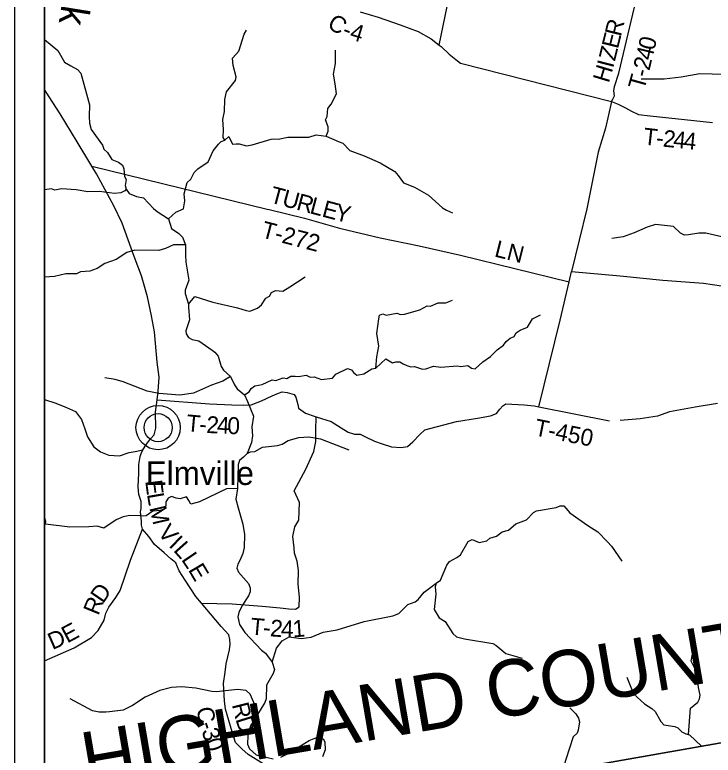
# Model space of a CAD drawing. Extents: x 0 to 34, y 0 to 22.
# Drawn here: x 23.917 to 26.267, y 14.865 to 17.356 of the extents above; entities that cross this region are included whole.
import ezdxf

# ---------------------------------------------------------------- set-up
doc = ezdxf.new("R2010")
doc.units = 0
for name, color, linetype in [('GM_X_Adjacent_County', 7, 'Continuous'), ('GM_X_Adjacent_County_Text', 7, 'Continuous'), ('GM_X_County', 7, 'Continuous'), ('GM_X_County_Road', 7, 'Continuous'), ('GM_X_County_Road_Text', 7, 'Continuous'), ('GM_X_Minor_River', 7, 'Continuous'), ('GM_X_Minor_River_Text', 7, 'Continuous'), ('GM_X_Township', 7, 'Continuous'), ('GM_X_Township_Road', 7, 'Continuous'), ('GM_X_Township_Road_Text', 7, 'Continuous'), ('GM_X_Township_ROW', 7, 'Continuous'), ('GM_X_Unincorporated', 7, 'Continuous'), ('GM_X_Unincorporated_Location', 7, 'Continuous'), ('GM_X_Unincorporated_Text', 7, 'Continuous'), ('SH_Data', 7, 'Continuous')]:
    doc.layers.add(name, color=color, linetype=linetype)

msp = doc.modelspace()

# ---------------------------------------------------------------- linework, layer by layer
at = {"layer": 'GM_X_Adjacent_County'}
msp.add_lwpolyline([(30.8167, 15.0595), (30.2392, 15.0941), (29.7209, 15.1252), (29.5448, 15.1357), (28.5345, 15.206), (28.3274, 15.217), (27.9456, 15.2665), (27.6234, 15.1875), (26.4461, 14.9325), (26.4085, 14.9262), (24.8262, 14.6485), (24.6978, 14.628), (24.0167, 14.5214)], dxfattribs=at)
at = {"layer": 'GM_X_County'}
for points in [[(29.025, 20.9), (24.0167, 20.9), (24.0167, 14.5214)], [(24.0167, 14.5214), (24.6978, 14.628), (24.8262, 14.6485), (26.4085, 14.9262), (26.4461, 14.9325), (27.6234, 15.1875), (27.9456, 15.2665), (27.9998, 15.5735), (28.0039, 15.594), (28.1843, 16.461), (28.2182, 16.6548), (28.4154, 17.5565), (28.5665, 18.3656), (28.8745, 20.061), (28.9523, 20.4546), (29.025, 20.9)]]:
    msp.add_lwpolyline(points, dxfattribs=at)
at = {"layer": 'GM_X_County_Road'}
for points in [[(25.0789, 17.3659), (25.1397, 17.3485), (25.213, 17.322), (25.2738, 17.3003), (25.3176, 17.2748), (25.3447, 17.254), (25.3515, 17.2488), (25.3786, 17.2235), (25.4003, 17.2055), (25.416, 17.193), (25.9245, 17.064), (25.9043, 16.9743), (25.8794, 16.8937), (25.8419, 16.7033), (25.7902, 16.4928), (25.9534, 16.4775), (26.0976, 16.4631), (26.2341, 16.4526), (26.2949, 16.4439)], [(24.7521, 14.8359), (24.7018, 14.8675), (24.6801, 14.886), (24.6598, 14.9079), (24.6482, 14.9435), (24.6257, 15.0196), (24.6218, 15.0477), (24.6191, 15.1065), (24.6249, 15.1445), (24.6278, 15.1726), (24.6337, 15.1954), (24.6389, 15.2193), (24.641, 15.2383), (24.6398, 15.2542), (24.637, 15.2694), (24.6114, 15.2977), (24.5447, 15.3763), (24.5255, 15.3989), (24.4898, 15.4533), (24.4703, 15.4851), (24.4587, 15.5116), (24.442, 15.5259), (24.4191, 15.5455), (24.3863, 15.5741), (24.3675, 15.6006), (24.3461, 15.6259), (24.3434, 15.6391), (24.3425, 15.6524), (24.3401, 15.6839), (24.3415, 15.6945), (24.3414, 15.7181), (24.3336, 15.7423), (24.3319, 15.7673), (24.3339, 15.8136), (24.3345, 15.8429), (24.3381, 15.8695), (24.3415, 15.8801), (24.3478, 15.8923), (24.3594, 15.9117), (24.3734, 15.9296), (24.3854, 15.9426), (24.391, 15.9654), (24.3898, 16.0193), (24.3955, 16.0607), (24.3993, 16.0884), (24.4024, 16.137), (24.3956, 16.1878), (24.3862, 16.2891), (24.3771, 16.3437), (24.3631, 16.407), (24.3425, 16.4778), (24.3178, 16.5426), (24.2777, 16.6547), (24.2504, 16.7133), (24.1916, 16.8211), (24.1762, 16.8466), (24.1269, 16.9281), (24.0698, 17.0227), (24.0319, 17.0797), (24.0167, 17.1044)], [(24.0167, 16.0622), (24.0548, 16.0491), (24.0902, 16.0349), (24.121, 16.0211), (24.1409, 15.9946), (24.1521, 15.9624), (24.1613, 15.9363), (24.1828, 15.9027), (24.2049, 15.8861), (24.2334, 15.8741), (24.2687, 15.8721), (24.3012, 15.8829), (24.3213, 15.8868), (24.3478, 15.8923)]]:
    msp.add_lwpolyline(points, dxfattribs=at)
at = {"layer": 'GM_X_Minor_River'}
for points in [[(24.6238, 16.9343), (24.6174, 16.9427), (24.6192, 16.97), (24.6165, 17.0038), (24.6221, 17.0306), (24.6229, 17.0715), (24.6295, 17.0965), (24.6594, 17.1345), (24.6611, 17.147), (24.6512, 17.1854), (24.6496, 17.21), (24.6706, 17.2341), (24.6886, 17.2907), (24.6959, 17.3039)], [(24.0167, 17.2728), (24.0615, 17.2355), (24.0838, 17.1966), (24.1049, 17.1843), (24.1279, 17.1719), (24.1391, 17.1597), (24.1675, 17.0529), (24.1668, 17.0139), (24.1681, 16.9919), (24.1735, 16.9698), (24.212, 16.9179), (24.2168, 16.9042), (24.2284, 16.8927), (24.2437, 16.8687), (24.2651, 16.8605), (24.2787, 16.8498), (24.2838, 16.8376), (24.2862, 16.8118), (24.291, 16.8019), (24.2882, 16.7811), (24.2915, 16.7693), (24.3016, 16.7552), (24.3257, 16.7451), (24.3495, 16.7407), (24.3839, 16.7047), (24.3959, 16.6944), (24.4335, 16.6698), (24.4445, 16.6371), (24.469, 16.6198), (24.4806, 16.6083), (24.4909, 16.5824), (24.4909, 16.5483), (24.4918, 16.5237), (24.5018, 16.4626), (24.4905, 16.4293), (24.49, 16.4187), (24.501, 16.3826), (24.5013, 16.3727), (24.5047, 16.3299), (24.4926, 16.2925), (24.4936, 16.2826), (24.5011, 16.2697), (24.5139, 16.2639), (24.5365, 16.2591), (24.5805, 16.228), (24.5902, 16.2214), (24.6007, 16.2069), (24.611, 16.1731), (24.6184, 16.1609), (24.6428, 16.1387), (24.6561, 16.1105), (24.6651, 16.0979), (24.6891, 16.0768), (24.7002, 16.0544), (24.7194, 16.006), (24.7141, 15.9701), (24.7161, 15.9394), (24.7136, 15.9167), (24.6989, 15.8797), (24.6859, 15.8677), (24.6725, 15.8564)], [(26.5192, 17.2363), (26.4958, 17.2388), (26.4737, 17.2314), (26.4206, 17.1774), (26.3932, 17.1633), (26.3477, 17.1538), (26.2218, 17.157), (26.1593, 17.1462), (26.1017, 17.1389), (26.0249, 17.1392)], [(24.964, 16.9473), (24.971, 16.965), (24.9712, 16.9794), (24.9623, 17.0023), (24.9677, 17.0143), (24.9695, 17.0405), (24.981, 17.0548), (24.9995, 17.0898), (24.9945, 17.1232), (24.9896, 17.1566), (24.9956, 17.1926), (24.9957, 17.2373)], [(24.4335, 16.6698), (24.4591, 16.6919), (24.4842, 16.7026), (24.4886, 16.7299), (24.4869, 16.7541), (24.4964, 16.7923), (24.5094, 16.8028), (24.5198, 16.8251), (24.5324, 16.8378), (24.5678, 16.8617), (24.5837, 16.8987), (24.6017, 16.9209), (24.6116, 16.9295), (24.6238, 16.9343), (24.6371, 16.9463), (24.6494, 16.9208), (24.6619, 16.9215), (24.6717, 16.9221), (24.6962, 16.9151), (24.7159, 16.9183), (24.7789, 16.9374), (24.7884, 16.9392), (24.8024, 16.9371), (24.8354, 16.944), (24.9061, 16.9448), (24.9304, 16.9518), (24.964, 16.9473), (25.0081, 16.929), (25.0209, 16.924), (25.0441, 16.8991), (25.0928, 16.882), (25.1459, 16.858), (25.1955, 16.8283), (25.2068, 16.8153), (25.225, 16.7905), (25.2612, 16.7765), (25.3083, 16.7495), (25.3555, 16.7062), (25.3694, 16.6985), (25.3894, 16.6899)], [(24.2915, 16.7693), (24.2873, 16.7637), (24.274, 16.757), (24.2527, 16.7545), (24.2021, 16.7615), (24.162, 16.76), (24.1235, 16.7668), (24.0743, 16.7703), (24.0519, 16.7656), (24.0406, 16.7703), (24.0167, 16.7671)], [(26.3155, 16.605), (26.2426, 16.6209), (26.2188, 16.6211), (26.1832, 16.6154), (26.1703, 16.6151), (26.1567, 16.6217), (26.1331, 16.6435), (26.073, 16.6502), (26.0442, 16.6418), (26.0012, 16.6225), (25.9644, 16.6085), (25.9262, 16.6035)], [(24.4909, 16.5824), (24.4508, 16.5817), (24.4242, 16.5694), (24.401, 16.5632), (24.3205, 16.5636), (24.2935, 16.5559), (24.2581, 16.5332), (24.2194, 16.5191), (24.1942, 16.5023), (24.1692, 16.4935), (24.1374, 16.4911), (24.1245, 16.4845), (24.0889, 16.484), (24.0506, 16.4757), (24.0167, 16.4738)], [(24.501, 16.3826), (24.5221, 16.4085), (24.5825, 16.3894), (24.6663, 16.37), (24.6953, 16.3606), (24.7081, 16.359), (24.7332, 16.3689), (24.7469, 16.3802), (24.7615, 16.4024), (24.7741, 16.4091), (24.7806, 16.4212), (24.7939, 16.4279), (24.8185, 16.4265), (24.8421, 16.4406), (24.8939, 16.4746)], [(25.1315, 16.1672), (25.1345, 16.2051), (25.1421, 16.2406), (25.1353, 16.2839), (25.1415, 16.3335), (25.1435, 16.3456), (25.1549, 16.35), (25.1669, 16.3454), (25.2022, 16.3522), (25.215, 16.3479), (25.2279, 16.3485), (25.2791, 16.3628), (25.3042, 16.3766), (25.3159, 16.3753), (25.341, 16.3868), (25.3671, 16.387), (25.3891, 16.3955)], [(24.6891, 16.0768), (24.7055, 16.088), (24.7124, 16.0982), (24.7246, 16.1075), (24.7488, 16.1122), (24.7827, 16.1278), (24.7947, 16.1258), (24.8198, 16.135), (24.8326, 16.1319), (24.846, 16.1405), (24.8603, 16.1407), (24.8717, 16.1387), (24.8975, 16.1434), (24.911, 16.1372), (24.9239, 16.1374), (24.9488, 16.1285), (24.9863, 16.1334), (24.9974, 16.1469), (25.0365, 16.1662), (25.0501, 16.1619), (25.0561, 16.152), (25.0681, 16.1436), (25.0908, 16.1483), (25.1182, 16.1651), (25.1315, 16.1672), (25.1651, 16.1987), (25.1873, 16.1849), (25.1987, 16.1885), (25.2119, 16.188), (25.2236, 16.1822), (25.236, 16.1757), (25.2492, 16.1717), (25.2617, 16.1727), (25.2881, 16.1642), (25.2995, 16.1644), (25.3253, 16.1733), (25.3498, 16.1707), (25.4051, 16.1751), (25.4176, 16.1727), (25.4414, 16.1759), (25.4531, 16.1675), (25.4663, 16.1647), (25.4911, 16.1883), (25.5174, 16.2059), (25.5396, 16.2291), (25.5613, 16.2441), (25.5698, 16.2573), (25.5831, 16.2681), (25.5975, 16.274), (25.6041, 16.2861), (25.6174, 16.2954), (25.6417, 16.3054), (25.6587, 16.3333), (25.6853, 16.3467)], [(24.6428, 16.1387), (24.6165, 16.123), (24.5789, 16.1097), (24.5181, 16.0827), (24.4723, 16.0767), (24.4012, 16.0815), (24.3619, 16.0899), (24.2809, 16.1214), (24.2545, 16.1292), (24.2197, 16.1345)], [(26.2812, 16.0479), (26.2066, 16.0361), (26.1198, 16.0207), (26.0795, 16.0055), (26.0212, 15.9966), (25.9538, 15.9912)], [(24.6989, 15.8797), (24.7103, 15.8852), (24.7243, 15.887), (24.7502, 15.9015), (24.8009, 15.9071), (24.8161, 15.9119), (24.8363, 15.9234), (24.8723, 15.9333), (24.906, 15.9356), (24.9449, 15.9288), (25.0406, 15.8922)], [(24.6725, 15.8564), (24.6682, 15.8428), (24.6659, 15.7618), (24.6599, 15.7258), (24.6679, 15.6973), (24.6837, 15.6418), (24.6894, 15.608), (24.6886, 15.5641), (24.6838, 15.5433), (24.6738, 15.5195), (24.6676, 15.5071), (24.664, 15.4946), (24.6696, 15.4809), (24.7033, 15.4427), (24.7092, 15.4275), (24.709, 15.415), (24.7036, 15.401), (24.6813, 15.3682), (24.6701, 15.3449), (24.6677, 15.3309), (24.6731, 15.305), (24.6907, 15.2772), (24.7465, 15.2187), (24.7607, 15.2087), (24.7831, 15.1774), (24.7901, 15.1534), (24.7858, 15.1402), (24.7638, 15.1002), (24.763, 15.0544), (24.7583, 15.0427), (24.7332, 15.0019)], [(24.6659, 15.7618), (24.6288, 15.761), (24.5384, 15.7175), (24.5088, 15.7095), (24.5025, 15.7217), (24.4946, 15.7346), (24.473, 15.728), (24.4594, 15.7293), (24.4443, 15.7355), (24.4322, 15.73), (24.4252, 15.7179), (24.4251, 15.705), (24.4189, 15.6926), (24.406, 15.6885), (24.381, 15.6865), (24.3582, 15.6701), (24.3476, 15.6694), (24.3374, 15.6706), (24.3037, 15.671), (24.2813, 15.667), (24.2582, 15.6563), (24.2167, 15.629), (24.194, 15.6353), (24.1656, 15.6329), (24.1017, 15.632), (24.0197, 15.6427), (24.0167, 15.6411)], [(25.3351, 15.4434), (25.3492, 15.4538), (25.3701, 15.5043), (25.379, 15.5171), (25.4041, 15.5305), (25.417, 15.5387), (25.4424, 15.584), (25.4561, 15.5903), (25.4791, 15.5802), (25.5049, 15.586), (25.5156, 15.5946), (25.5372, 15.602), (25.557, 15.6169), (25.5775, 15.622), (25.6027, 15.6438), (25.6384, 15.6571), (25.6617, 15.6818), (25.672, 15.687), (25.7383, 15.6985), (25.7516, 15.7037), (25.7641, 15.7043), (25.7839, 15.6803), (25.8455, 15.6372), (25.879, 15.6168), (25.9108, 15.5831), (25.9243, 15.5686), (25.9594, 15.5179)], [(24.0197, 15.6427), (24.0209, 15.651), (24.0167, 15.6655)], [(24.7831, 15.1774), (24.7976, 15.2246), (24.816, 15.2494), (24.8403, 15.2636), (24.88, 15.2575), (24.9141, 15.2625), (24.9548, 15.2791), (25.0014, 15.2866), (25.0925, 15.3149), (25.1891, 15.3337), (25.2093, 15.3422), (25.2394, 15.3722), (25.2637, 15.3807), (25.2737, 15.3886), (25.294, 15.4134), (25.3351, 15.4434)], [(25.3351, 15.4434), (25.3312, 15.4312), (25.334, 15.4062), (25.3278, 15.3551), (25.3446, 15.3276), (25.3649, 15.3145), (25.3906, 15.2745), (25.403, 15.2634), (25.4301, 15.2559), (25.5253, 15.2406), (25.5355, 15.2355), (25.5696, 15.2071), (25.6236, 15.1918)], [(26.1842, 14.9342), (26.1903, 15.023), (26.2152, 15.0428), (26.2211, 15.0548), (26.2228, 15.0673), (26.2178, 15.0928), (26.2151, 15.1133), (26.2067, 15.1374), (26.2055, 15.1571), (26.1929, 15.1815), (26.1967, 15.205), (26.1959, 15.2282)], [(25.9766, 15.1277), (25.9985, 15.0712), (26.0356, 15.0377), (26.0607, 15.0222), (26.072, 15.0118), (26.0904, 14.9782), (26.1009, 14.9666), (26.1372, 14.9616), (26.1473, 14.9565), (26.1612, 14.9438), (26.1743, 14.9364), (26.1868, 14.9336), (26.228, 14.895)], [(24.7332, 15.0019), (24.7286, 15.0244), (24.7083, 15.0701), (24.6955, 15.0827), (24.6661, 15.0857), (24.5956, 15.0784), (24.5801, 15.0789), (24.5254, 15.0908), (24.4777, 15.0951), (24.444, 15.0924), (24.4042, 15.0822), (24.3552, 15.0603), (24.3125, 15.0323), (24.281, 15.0163), (24.2348, 15.0103), (24.2227, 15.0101), (24.2, 15.0099), (24.1784, 15.0139), (24.1028, 15.0545)], [(25.7842, 15.0245), (25.8051, 15.0045), (25.814, 14.9896), (25.8173, 14.9774), (25.8127, 14.949), (25.8088, 14.9388), (25.7953, 14.9269), (25.7704, 14.8502), (25.7664, 14.8363), (25.7552, 14.8123)], [(24.7332, 15.0019), (24.7095, 14.9636), (24.7005, 14.9315), (24.7002, 14.9019), (24.7065, 14.8863), (24.729, 14.8664), (24.786, 14.8529)], [(24.8114, 14.8587), (24.8342, 14.8699), (24.9069, 14.9143), (24.9301, 14.9231), (24.9429, 14.9245), (24.9557, 14.9183), (24.9598, 14.9088), (24.9611, 14.883), (24.9525, 14.8592)]]:
    msp.add_lwpolyline(points, dxfattribs=at)
at = {"layer": 'GM_X_Township'}
for points in [[(29.025, 20.9), (24.0167, 20.9), (24.0167, 14.5214)], [(24.0167, 14.5214), (24.6978, 14.628), (24.8262, 14.6485), (26.4085, 14.9262), (26.4461, 14.9325), (27.6234, 15.1875), (27.9456, 15.2665), (27.9998, 15.5735), (28.0039, 15.594), (28.1843, 16.461), (28.2182, 16.6548), (28.4154, 17.5565), (28.5665, 18.3656), (28.8745, 20.061), (28.9523, 20.4546), (29.025, 20.9)]]:
    msp.add_lwpolyline(points, dxfattribs=at)
at = {"layer": 'GM_X_Township_Road'}
for points in [[(25.9245, 17.064), (25.929, 17.0724), (25.9347, 17.0835), (25.9326, 17.1001), (25.9344, 17.1153), (25.9493, 17.1591), (26.0121, 17.4252), (26.0369, 17.5221), (26.0511, 17.6023), (26.0688, 17.9748), (26.0814, 18.2937)], [(25.3447, 17.254), (25.3719, 17.3837), (25.4361, 17.6524), (25.4386, 17.6885), (25.4452, 17.7098), (25.4566, 17.719), (25.4778, 17.7131), (25.4999, 17.709), (25.5124, 17.7087), (25.5234, 17.7103), (25.5313, 17.7191), (25.5342, 17.7384), (25.5513, 17.9589)], [(25.9245, 17.064), (25.9466, 17.0554), (25.9713, 17.0427), (25.9919, 17.0318), (26.0154, 17.021), (26.0549, 17.0155), (26.2644, 16.994)], [(24.766, 16.7022), (24.7724, 16.7006), (24.8911, 16.6715), (25.0091, 16.6385), (25.1457, 16.6059), (25.2774, 16.5782), (25.4166, 16.5467), (25.782, 16.4574)], [(24.3955, 16.0607), (24.5724, 16.047), (24.6468, 16.044), (24.6878, 16.0424), (24.7116, 16.0433), (24.7472, 16.0575), (24.7831, 16.0745), (24.8035, 16.0833), (24.816, 16.0872), (24.8331, 16.085), (24.8563, 16.0787), (24.8628, 16.07), (24.8686, 16.0446), (24.8717, 16.0325), (24.8954, 16.0159), (24.9273, 16.0048), (24.931, 16.0036), (24.9816, 15.9876), (25.0147, 15.9666), (25.0387, 15.9512), (25.0593, 15.9445), (25.0786, 15.945), (25.0972, 15.9356), (25.1273, 15.9214), (25.1527, 15.9124), (25.1847, 15.902), (25.2169, 15.9003), (25.2377, 15.9034), (25.2562, 15.9195), (25.2792, 15.9435), (25.2969, 15.9592), (25.4033, 15.9876), (25.4741, 15.9994), (25.5173, 16.0069), (25.5374, 16.0146), (25.5494, 16.0287), (25.5588, 16.0409), (25.569, 16.047), (25.6305, 16.0432), (25.6646, 16.0404), (25.6799, 16.0375), (25.7518, 16.3282), (25.782, 16.4574), (25.7902, 16.4928)], [(25.6799, 16.0375), (25.9184, 15.9904)], [(24.0167, 15.1826), (24.1165, 15.2257), (24.1747, 15.261), (24.1968, 15.2844), (24.2174, 15.3196), (24.2232, 15.3427), (24.2335, 15.3628), (24.2568, 15.3953), (24.2717, 15.4195), (24.3059, 15.5207), (24.3461, 15.6259)], [(24.5447, 15.3763), (24.6478, 15.374), (24.7486, 15.3666), (24.81, 15.3603), (24.8391, 15.3574), (24.8615, 15.3562), (24.8741, 15.3637), (24.8742, 15.3964), (24.8706, 15.4408), (24.8712, 15.4867), (24.8668, 15.5175), (24.8582, 15.5445), (24.8564, 15.5616)]]:
    msp.add_lwpolyline(points, dxfattribs=at)
at = {"layer": 'GM_X_Township_ROW'}
for points in [[(24.1762, 16.8466), (24.7656, 16.7023), (24.766, 16.7022)], [(24.8564, 15.5616), (24.8563, 15.5621), (24.8521, 15.6011), (24.859, 15.6333), (24.8728, 15.656), (24.875, 15.7148), (24.8573, 15.754), (24.896, 15.8267), (24.9232, 15.8869), (24.9298, 15.9206), (24.93, 15.9582), (24.931, 16.0036)]]:
    msp.add_lwpolyline(points, dxfattribs=at)
at = {"layer": 'GM_X_Unincorporated'}
for radius in [0.0744, 0.0472]:
    msp.add_circle((24.3989, 15.9669), radius, dxfattribs=at)
at = {"layer": 'GM_X_Unincorporated_Location'}
msp.add_line((24.3989, 15.9669), (24.3989, 15.9669), dxfattribs=at)
at = {"layer": 'SH_Data'}
for points in [[(23.9167, 21), (30.9167, 21), (30.9167, 14), (23.9167, 14)], [(24.0167, 20.9), (30.8167, 20.9), (30.8167, 14.1), (24.0167, 14.1)]]:
    msp.add_lwpolyline(points, close=True, dxfattribs=at)

# ---------------------------------------------------------------- texts
at = {"layer": 'GM_X_Adjacent_County_Text'}
msp.add_text('HIGHLAND COUNTY', height=0.189394, rotation=9.7068, dxfattribs=at).set_placement((24.1589, 14.7512))
at = {"layer": 'GM_X_County_Road_Text'}
for s, rotation, p in [('C', 327.8353, (24.9646, 17.3151)), ('4', 342.8142, (25.0405, 17.2751)), ('-', 338.7751, (25.0147, 17.285)), ('E', 277.3616, (24.3554, 15.7877)), ('L', 279.6904, (24.3612, 15.7431)), ('M', 283.1153, (24.3691, 15.6976)), ('V', 309.3875, (24.3953, 15.6127)), ('I', 316.3635, (24.4321, 15.5686)), ('L', 311.5189, (24.4481, 15.5534)), ('L', 304.1406, (24.4751, 15.5231)), ('E', 300.722, (24.4985, 15.4887)), ('C', 281.0551, (24.5272, 15.0221)), ('R', 284.0665, (24.6466, 15.0349)), ('D', 287.2764, (24.6588, 14.9863)), ('-', 287.2584, (24.5378, 14.9698)), ('3', 287.0163, (24.5447, 14.9476)), ('0', 288.5402, (24.5555, 14.9125))]:
    msp.add_text(s, height=0.0568, rotation=rotation, dxfattribs=at).set_placement(p)
at = {"layer": 'GM_X_Minor_River_Text'}
msp.add_text('Fork', height=0.0947, rotation=260.8961, dxfattribs=at).set_placement((24.1045, 17.5797))
at = {"layer": 'GM_X_Township_Road_Text'}
for s, height, rotation, p in [('R', 0.0568, 76.307, (25.9563, 17.2805)), ('E', 0.0568, 76.3053, (25.9462, 17.2392)), ('0', 0.0568, 76.3757, (26.0686, 17.234)), ('Z', 0.0568, 76.2259, (25.9361, 17.1978)), ('4', 0.0568, 76.3422, (26.0603, 17.2)), ('2', 0.0568, 76.1735, (26.0519, 17.1658)), ('I', 0.0568, 75.5223, (25.9301, 17.1745)), ('H', 0.0568, 73.3681, (25.9152, 17.1244)), ('-', 0.0568, 75.8628, (26.0462, 17.1428)), ('T', 0.0568, 74.5396, (26.0345, 17.1005)), ('T', 0.0568, 353.4804, (26.0296, 16.9199)), ('2', 0.0568, 354.2559, (26.0959, 16.9126)), ('-', 0.0568, 354.1339, (26.0725, 16.915)), ('4', 0.0568, 354.2837, (26.1307, 16.9091)), ('4', 0.0568, 354.288, (26.1656, 16.9056)), ('T', 0.0568, 345.0012, (24.7718, 16.7251)), ('U', 0.0568, 344.9954, (24.8129, 16.7141)), ('R', 0.0568, 344.9987, (24.8612, 16.7011)), ('L', 0.0568, 345.0012, (24.9062, 16.689)), ('E', 0.0568, 345.0844, (24.9474, 16.678)), ('Y', 0.0568, 346.5726, (24.99, 16.6667)), ('T-272', 0.05682, 345.4273, (24.7429, 16.6078)), ('LN', 0.05682, 345.9638, (25.5278, 16.5433)), ('T', 0.0568, 354.7943, (24.4923, 15.9551)), ('2', 0.0568, 356.7853, (24.5601, 15.9494)), ('4', 0.0568, 357.7466, (24.596, 15.9474)), ('0', 0.0568, 358.0486, (24.6313, 15.946)), ('T-450', 0.05682, 348.6899, (25.6622, 15.9416)), ('-', 0.0568, 355.8222, (24.5358, 15.9512)), ('D', 0.0568, 55.6087, (24.2137, 15.3729)), ('R', 0.0568, 67.626, (24.1975, 15.3325)), ('T', 0.0568, 354.8847, (24.7078, 15.271)), ('2', 0.0568, 355.7773, (24.7743, 15.2651)), ('1', 0.0568, 3.9968, (24.8531, 15.2614)), ('E', 0.0568, 28.0045, (24.0932, 15.2405)), ('4', 0.0568, 358.2005, (24.8118, 15.2624)), ('D', 0.0568, 23.6965, (24.0433, 15.2184)), ('-', 0.0568, 355.0613, (24.7503, 15.2672))]:
    msp.add_text(s, height=height, rotation=rotation, dxfattribs=at).set_placement(p)
at = {"layer": 'GM_X_Unincorporated_Text'}
msp.add_text('Elmville', height=0.07898, rotation=0, dxfattribs=at).set_placement((24.3574, 15.7741))

doc.saveas('drawing.dxf')
